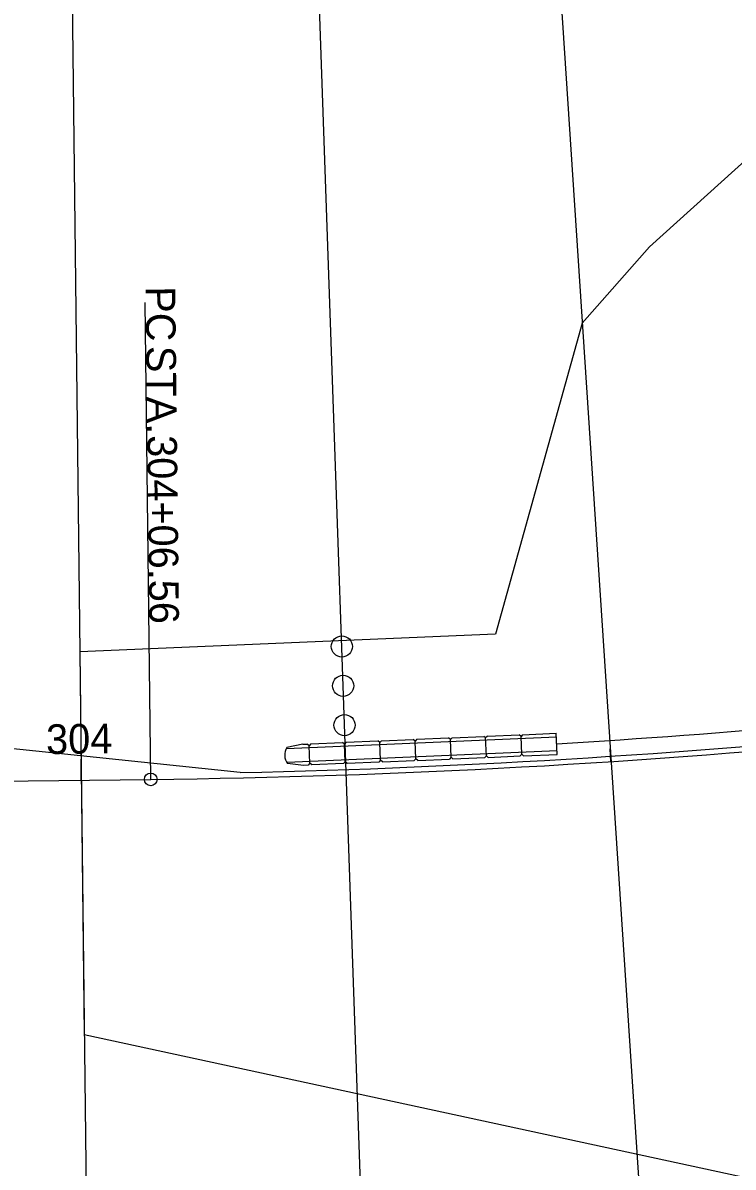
# Model space of a CAD drawing. Extents: x 153902 to 157473, y 413085 to 414252.
# Drawn here: x 154196.6 to 154263.6, y 413658.2 to 413766.1 of the extents above; entities that cross this region are included whole.
import ezdxf

# ---------------------------------------------------------------- set-up
doc = ezdxf.new("R2010")
doc.units = 0
for name, color, linetype in [('GE_P_Alignment', 7, 'Continuous'), ('GE_P_Alignment_100_Cardinal_Points', 7, 'Continuous'), ('PF_X_Ground_Line', 7, 'Continuous'), ('PV_X_Text', 7, 'Continuous'), ('SV_X_Text', 7, 'Continuous'), ('UT_X_Electric_Cells', 7, 'Continuous')]:
    doc.layers.add(name, color=color, linetype=linetype)

msp = doc.modelspace()

# ---------------------------------------------------------------- linework, layer by layer
at = {"layer": 'GE_P_Alignment'}
msp.add_line((154144.98, 413694.03), (154208.68, 413694.77), dxfattribs=at)
msp.add_arc((154199.36, 414496.89), 802.17, 270.66569, 280.65583, dxfattribs=at)
at = {"layer": 'GE_P_Alignment_100_Cardinal_Points'}
msp.add_line((154208.68, 413694.77), (154208.16, 413739.77), dxfattribs=at)
msp.add_circle((154208.68, 413694.77), 0.6, dxfattribs=at)
at = {"layer": 'PF_X_Ground_Line'}
for p, q in [((154252.08, 413696.45), (154252, 413697.65)), ((154202.12, 413694.69), (154202.1, 413696.69))]:
    msp.add_line(p, q, dxfattribs=at)
at = {"layer": 'PV_X_Text'}
for p, q in [((154244.2, 413816.19), (154259.97, 413576.71)), ((154231.27, 413575.27), (154222.96, 413815.12)), ((154200.73, 413814.69), (154203.52, 413574.7))]:
    msp.add_line(p, q, dxfattribs=at)
at = {"layer": 'SV_X_Text'}
for p, q in [((154217.1, 413695.41), (154142.21, 413703.24)), ((154221.47, 413697.69), (154246.93, 413698.8)), ((154223.77, 413698.12), (154226.77, 413698.25)), ((154226.94, 413698.1), (154226.77, 413698.25)), ((154227.1, 413698.27), (154226.94, 413698.1)), ((154227.1, 413698.27), (154230.1, 413698.4)), ((154230.27, 413698.24), (154230.1, 413698.4)), ((154230.43, 413698.41), (154230.27, 413698.24)), ((154230.35, 413696.58), (154230.27, 413698.24)), ((154230.43, 413698.41), (154233.43, 413698.54)), ((154233.6, 413698.39), (154233.43, 413698.54)), ((154233.76, 413698.56), (154233.6, 413698.39)), ((154233.68, 413696.72), (154233.6, 413698.39)), ((154233.76, 413698.56), (154236.76, 413698.69)), ((154236.93, 413698.53), (154236.76, 413698.69)), ((154237.09, 413698.7), (154236.93, 413698.53)), ((154237.01, 413696.87), (154236.93, 413698.53)), ((154237.09, 413698.7), (154240.09, 413698.83)), ((154240.26, 413698.68), (154240.09, 413698.83)), ((154240.42, 413698.85), (154240.26, 413698.68)), ((154240.34, 413697.01), (154240.26, 413698.68)), ((154240.42, 413698.85), (154243.42, 413698.98)), ((154243.6, 413698.82), (154243.42, 413698.98)), ((154243.75, 413698.99), (154243.6, 413698.82)), ((154243.67, 413697.16), (154243.6, 413698.82)), ((154243.75, 413698.99), (154246.92, 413699.13)), ((154247.01, 413697.13), (154246.92, 413699.13)), ((154223.01, 413698.09), (154221.52, 413697.78)), ((154246.99, 413697.47), (154221.53, 413696.36)), ((154223.01, 413698.09), (154223.44, 413698.11)), ((154223.61, 413697.95), (154223.44, 413698.11)), ((154223.77, 413698.12), (154223.61, 413697.95)), ((154223.69, 413696.29), (154223.61, 413697.95)), ((154227.02, 413696.43), (154226.94, 413698.1)), ((154243.67, 413697.16), (154243.51, 413696.98)), ((154243.84, 413697), (154243.67, 413697.16)), ((154243.84, 413697), (154247.01, 413697.13)), ((154223.09, 413696.09), (154221.58, 413696.28)), ((154223.53, 413696.11), (154223.09, 413696.09)), ((154223.69, 413696.29), (154223.53, 413696.11)), ((154223.86, 413696.13), (154223.69, 413696.29)), ((154226.86, 413696.26), (154223.86, 413696.13)), ((154227.02, 413696.43), (154226.86, 413696.26)), ((154227.19, 413696.27), (154227.02, 413696.43)), ((154230.19, 413696.4), (154227.19, 413696.27)), ((154230.35, 413696.58), (154230.19, 413696.4)), ((154230.52, 413696.42), (154230.35, 413696.58)), ((154230.52, 413696.42), (154233.52, 413696.55)), ((154233.68, 413696.72), (154233.52, 413696.55)), ((154233.85, 413696.56), (154233.68, 413696.72)), ((154233.85, 413696.56), (154236.85, 413696.69)), ((154237.01, 413696.87), (154236.85, 413696.69)), ((154237.18, 413696.71), (154237.01, 413696.87)), ((154237.18, 413696.71), (154240.18, 413696.84)), ((154240.34, 413697.01), (154240.18, 413696.84)), ((154240.51, 413696.85), (154240.34, 413697.01)), ((154240.51, 413696.85), (154243.51, 413696.98))]:
    msp.add_line(p, q, dxfattribs=at)
for centre in [(154226.7, 413707.31), (154226.82, 413703.6), (154226.95, 413699.89)]:
    msp.add_circle(centre, 1, dxfattribs=at)
for centre, radius, start, end in [((154199.36, 414496.89), 801.67, 271.26817, 280.65583), ((154199.36, 414496.89), 800.17, 273.4105, 280.28464), ((154222.65, 413697.07), 1.34, 148.3172, 216.6686)]:
    msp.add_arc(centre, radius, start, end, dxfattribs=at)
at = {"layer": 'UT_X_Electric_Cells'}
for points in [[(154249.36, 413737.82), (154255.7, 413745.02), (154291.76, 413777.57), (154317.86, 413759.14), (154358.14, 413727.79)], [(154249.36, 413737.82), (154241.2, 413708.46), (154201.98, 413706.81), (154202.4, 413670.72)], [(154202.4, 413670.72), (154326.58, 413643.87), (154381.35, 413615.96), (154411.04, 413642.76), (154403.51, 413708.45), (154396.28, 413732.77), (154358.14, 413727.79)]]:
    msp.add_lwpolyline(points, dxfattribs=at)

# ---------------------------------------------------------------- texts
at = {"layer": 'GE_P_Alignment_100_Cardinal_Points'}
for s, p in [('PC', (154208.18, 413741.27)), (' STA. ', (154208.23, 413736.69)), ('304+06.56', (154208.34, 413727.23))]:
    msp.add_text(s, height=2.8, rotation=270.6657, dxfattribs=at).set_placement(p)
at = {"layer": 'PF_X_Ground_Line'}
msp.add_text('304', height=2.8, rotation=0.6657, dxfattribs=at).set_placement((154198.82, 413697.16))

doc.saveas('drawing.dxf')
